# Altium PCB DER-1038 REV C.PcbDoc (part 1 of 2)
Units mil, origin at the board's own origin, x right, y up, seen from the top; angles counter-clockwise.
Board outline 9818.9 x 992.13 mil, 2 copper layers (TOP, BOTTOM), stack 10.4 mil thick; 94 components, 52 nets, 258 pads, 996 vias.
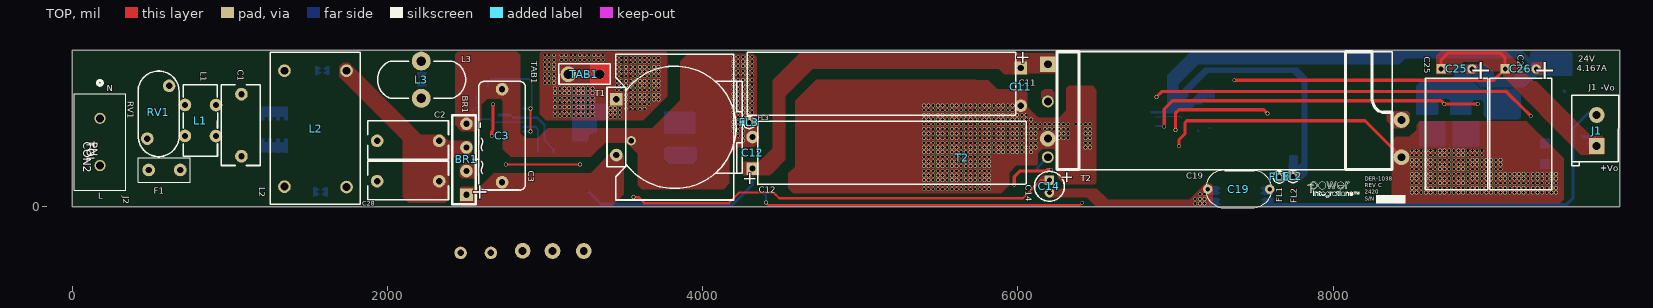
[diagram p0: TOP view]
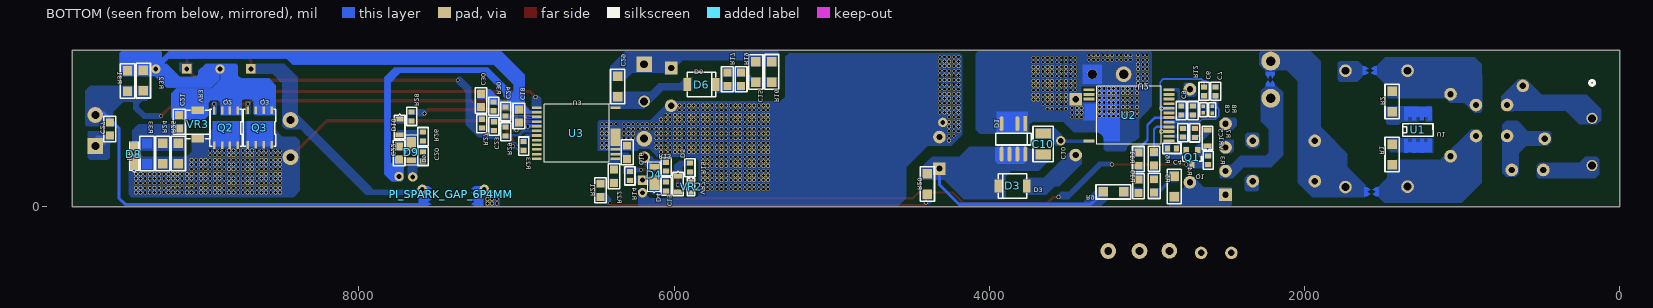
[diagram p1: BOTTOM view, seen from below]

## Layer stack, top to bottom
Top Solder: solder mask 0.4, Solder Resist, Dk 3.5
TOP: signal copper 1.2
Dielectric 1: core 8, FR-4, Dk 4.5
BOTTOM: signal copper 1.2
Bottom Solder: solder mask 0.4, Solder Resist, Dk 3.5

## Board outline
0,0 0,992.13 9818.9,992.13 9818.9,0

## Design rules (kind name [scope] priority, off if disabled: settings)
Clearance [All] p1: gap=10 ignorepadtopadclearanceinfootprint=FALSE
PlaneConnect [All] p1: planeconnectstyle=Direct reliefexpansion=20 reliefentries=4 reliefconductorwidth=10 reliefairgap=10
PolygonConnect [All] p1: connectstyle=Direct reliefconductorwidth=10 reliefentries=4 polygonreliefangle="90 Angle" airgapwidth=10
RoutingVias [All] p1: holewidth=28 width=50 viastyle="Through Hole" minholewidth=28 minwidth=50 maxholewidth=28 maxwidth=50
SolderMaskExpansion [All] p1: expansion=4 istentingtop=FALSE
Width [All] p1: maxlimit=10 minlimit=10 preferedwidth=10 impedanceprofiledriven=TRUE minimp=60.000000 maximp=60.000000 favimp=60.000000
29 further rules are at their usual default settings.

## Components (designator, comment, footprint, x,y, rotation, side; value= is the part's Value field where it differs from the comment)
BR1 "DISCRETE BRIDGE_+~~-_PIDAXBRIDG" PIDAXBRIDGED3K 2486,298.5 r90 top
C1 "CAP NP_PINPXCAPRAD13X6MM040_0.1" PINPXCAPRAD13X6MM040 1068.08,517.15 r270 top
C2 "CAP NP_PINPXCAPRAD13X6MM040_0.1" PINPXCAPRAD13X6MM040 2131.15,422.92 r180 top
C3 "CAP NP_PINPCAPRAD17P5X7P8X15MML" PINPCAPRAD17P5X7P8X15MMLS 2727,450.28 r90 top
C4 "CAP NP_PISMC0603_1 UF_UNISEM_RM" PISMC0603#1 2841,370 r180 bottom
C5 "CAP NP_PISMC0603_470 PF" PISMC0603#2 2771,469 r90 bottom
C6 "CAP NP_PISMC0603_1 UF_UNISEM_RM" PISMC0603#2 2637,732 r90 bottom
C7 "CAP NP_PISMC0603_0.1 UF_UNISEM_" PISMC0603#2 2564,732 r270 bottom
C8 "CAP NP_PISMR0402_1 UF_PISMR0402" PISMR0402 2641,616 r270 bottom
C9 "CAP NP_PISMC0603_470 PF" PISMC0603#2 2782,610 r270 bottom
C10 "CAP NP_PISMC1210_22 NF" PISMC1210 3658,396.75 r270 bottom
C11 "CAP POL_PIPOLCAPD395LS200D04017" PIPOLCAPD395LS200D0401705LH#1 5188.69,781.5 r270 top
C12 "CAP POL_PIPOLCAPD395LS200D04017" PIPOLCAPD395LS200D0401705LH#2 5147,340.5 r90 top
C13 "CAP NP_PISMC0603_NC_UNISEM_RMCF" PISMC0603#2 6051,129 r270 bottom
C14 "CAP POL_PI_POLCAP_D200_LS80_D03" PI_POLCAP_D200_LS80_D030 6201.37,131 r270 top
C15 "CAP NP_PISMC1206_2.2 NF_CAP_321" PISMC1206 5480.5,855 r90 bottom
C16 "CAP NP_PISMC0805_0.47 UF_UNISEM" PISMC0805 6298.37,345 r270 bottom
C18 "CAP NP_PISMC0805_2.2 UF" PISMC0805 6985.37,576 r270 bottom
C19 "CAP NP_PINPCAPRAD11X6MMD030_220" PINPCAPRAD11X6MMD030 7401.48,111.13 r0 top
C20 "CAP NP_PISMC0603_NC_UNISEM_RMCF" PISMC0603#2 7594,319 r270 bottom
C21 "CAP NP_PISMC0805_2200 PF_UNISEM" PISMC0805 9141,539 r90 bottom
C22 "CAP NP_PISMC0805_10 UF_UNISEM_R" PISMC0805 7745,341 r90 bottom
C23 "CAP NP_PISMC0603_22 NF_UNISEM_R" PISMC0603#2 7144,511 r270 bottom
C24 "CAP NP_PISMC0603_1 NF_UNISEM_RM" PISMC0603#2 7069,604 r270 bottom
C25 "CAP POL_PIPOLCAPCLYD10MMD30_680" PIPOLCAPCLYD10X18MMD30H 8783.89,509.83 r180 top
C26 "CAP POL_PIPOLCAPCLYD10MMD30_680" PIPOLCAPCLYD10X18MMD30H 9190.89,509.83 r180 top
C27 "CAP NP_PISMC0805_2.2 UF_UNISEM_" PISMC0805 9581,493 r270 bottom
C28 "CAP NP_PINPXCAPRAD13X6MM040_0.1" PINPXCAPRAD13X6MM040 2131.15,166.92 r180 top
C29 "CAP NP_PISMC1206_47 PF" PISMC1206 6358.5,763 r90 bottom
C30 "CAP NP_PISMC0805_2.2 UF" PISMC0805 7226,674 r90 bottom
D1 "DIODE_A1K8_PI_SM_DIODE_SO8C_LXA" PI_SM_DIODE_SO8C 3847,429 r0 bottom
D3 "DIODE_PISMDO221AA_STTH208UFY" PISMDO221AA#1 3852,132 r180 bottom
D4 "DIODE_PISMDDFLR120012_DFLR1200-" PISMDDFLR120012 6127,187 r90 bottom
D5 "DIODE_PISMSOD323_BAV19WS" PISMSOD323 5975,147.5 r90 bottom
D6 "DIODE_PISMDO221AA_GS1MFL-TP" PISMDO221AA#1 5826,775 r0 bottom
D8 "DIODE SCHOTTKY_PI_SM_SOD-123HE_" PI_SM_SOD-123HE 9428.5,319.94 r270 bottom
D9 "DIODE_PISMDDFLR120012_DFLR1200-" PISMDDFLR120012 7668,360 r270 bottom
D10 "DIODE_PISMSOD323_BAV19WS" PISMSOD323 7742,510.5 r90 bottom
F1 "FUSE_PI_RST_MICROFUSE_3.15 A_PI" PI_RST_MICROFUSE 582.9,233.08 r0 top
FL1 "FLYINGLEAD_PI_HOLE_30MIL_HOLE_3" PI_HOLE_30MIL 7659,188 r0 top
FL2 "FLYINGLEAD_PI_HOLE_30MIL_HOLE_3" PI_HOLE_30MIL 7746,191 r0 top
FL3 "FLYINGLEAD_PI_HOLE_30MIL_HOLE_3" PI_HOLE_30MIL 4295,534 r0 top
J1 "CON2_PI_TERM_BLOCK_2PIN_LS200_T" PI_TERM_BLOCK_2PIN_LS200 9663.75,483.5 r0 top
J2 "CON2_CONN_1707027_PXC_CON2" CONN_1707027_PXC 175,410.92 r270 top
L1 "TORRID 4P_14_23_PI_4P_LS5W4P8XD" PI_4P_LS5W4P8XD11P5MMD40 813,547 r269.91 top
L2 "INDUCTOR_4P_1-2_4-3_PIIND4P965X" PIIND4P965X571LS736X394D040 1542.5,498.5 r270 top
L3 "INDUCTOR_PI2P14DX6MMWD060_68 UH" PI2P14DX6MMWD060 2216.42,805.89 r270 top
PI_SPARK_GAP_6P4MM "" PI_SPARK_GAP_6P4MM#1 7413.63,116.31 r180.08 bottom
PI_SPARK_GAP_6P4MM "" PI_SPARK_GAP_6P4MM#2 7414.63,44 r179.99 bottom
Q1 "NPN_BEC_PISMSOT23123_1_MMBT4401" PISMSOT23123_1 2713.4,317.31 r0 bottom
Q2 "FET_N_SGD_123_4_5678_PISMPQFN5X" PISMPQFN5X6B 8843.5,502 r0 bottom
Q3 "FET_N_SGD_123_4_5678_PISMPQFN5X" PISMPQFN5X6B 8629.5,503 r0 bottom
R1 "R_PISMR1206_510 K" PISMR1206#1 1444.5,332 r270 bottom
R2 "R_PISMR1206_510 K" PISMR1206#1 1444.5,667 r270 bottom
R3 "R_PISMR0603_100 K" PISMR0603 2611,294.5 r270 bottom
R4 "R_PISMR1206_6.8 M" PISMR1206#1 2826.5,128 r90 bottom
R5 "R_PISMR0805_4.7 M_UNISEM_RMCF08" PISMR0805 2954,131.5 r90 bottom
R6 "R_PISMR0805_4.7 M_UNISEM_RMCF08" PISMR0805 2955,304.5 r270 bottom
R7 "R_PISMR0603_154 K_UNISEM_RMCF06" PISMR0603 2696,468.5 r90 bottom
R8 "R_PISMR0402_30.1 K" PISMR0402 2585,615 r90 bottom
R9 "R_PISMR1206_6.8 M" PISMR1206#2 3213,94.5 r180 bottom
R10 "R_PISMR0805_4.7 M_UNISEM_RMCF08" PISMR0805 3053,130.5 r270 bottom
R11 "R_PISMR0805_4.7 M_UNISEM_RMCF08" PISMR0805 3054,301.5 r90 bottom
R12 "R_PISMR0603_158 K_UNISEM_RMCF06" PISMR0603 2707,610.5 r90 bottom
R13 "R_PISMR0603_NC_UNISEM_RMCF0603U" PISMR0603 6051,253.5 r270 bottom
R14 "R_PISMR0603_5.1 K_UNISEM_RMCF06" PISMR0603 6281,194.5 r270 bottom
R15 "R_PISMR0603_100_UNISEM_RMCF0603" PISMR0603 5900,247.5 r270 bottom
R16 "R_PISMR1206_500 K" PISMR1206#1 5380.5,856 r90 bottom
R17 "R_PISMR0805_15_UNISEM_RMCF0805U" PISMR0805 5662,809.5 r270 bottom
R19 "R_PISMR0805_15_UNISEM_RMCF0805U" PISMR0805 5575,809.5 r270 bottom
R20 "R_PISMR1206_1.6 M" PISMR1206#1 4392.5,144 r90 bottom
R21 "R_PISMR0805_1.2 M_UNISEM_RMCF08" PISMR0805 6467.37,104.5 r270 bottom
R22 "R_PISMR0805_1.2 M_UNISEM_RMCF08" PISMR0805 6382,193.5 r270 bottom
R23 "R_PISMR0603_300_UNISEM_RMCF0603" PISMR0603 6955,384.5 r270 bottom
R24 "R_PISMR1206_15" PISMR1206#1 9244.5,337 r90 bottom
R25 "R_PISMR1206_15" PISMR1206#1 9145.5,338 r90 bottom
R26 "R_PISMR0603_NC_UNISEM_RMCF0603U" PISMR0603 7594,444.5 r270 bottom
R27 "R_PISMR0603_4.7 K_UNISEM_RMCF06" PISMR0603 7220,527.5 r90 bottom
R28 "R_PISMR0603_1.2 K_UNISEM_RMCF06" PISMR0603 7666,572.5 r270 bottom
R29 "R_PISMR0603_100 K" PISMR0603 7069,476.5 r270 bottom
R30 "R_PISMR0603_5.49 K_UNISEM_RMCF0" PISMR0603 7145,636.5 r270 bottom
R31 "R_PISMR1206_0.01" PISMR1206#1 9468.5,798 r90 bottom
R32 "R_PISMR1206_0.01" PISMR1206#1 9367.5,800 r90 bottom
R33 "R_PISMR1206_15" PISMR1206#3 9344.46,337 r90.04 bottom
RV1 "VARISTOR_PIDISC500X225LS335X140" PIDISC500X225LS335X140040 547.14,589.95 r270.1 top
T1 "BATQ23.2_4P/GENERIC_PI_BOBBIN_A" PI_BOBBIN_ATQ23_V_4PB 3822,505 r0 top
T2 "BEQ20_9P_PI_BOBBIN_EDR4110_9P_6" PI_BOBBIN_EDR4110_9P_6X3 7312.19,609 r0 top
TAB1 "CON1_2P_TAB_PI_CONN_QC_TAB_2PIN" PI_CONN_QC_TAB_2PIN_LS200 3250.44,840.94 r90.03 top
U1 "CAPZERO_PI_IC_SMD_SO8_CAPZERO_C" PI_IC_SMD_SO8_CAPZERO 1280.17,489.63 r180.1 bottom
U2 "HIPERPFS-4-INSOP24B_PI_IC_INSOP" PI_IC_INSOP24B 3114,580 r0 bottom
U3 "INNO4-QR_PI_IC_INSOP_24D_IPC_IN" PI_IC_INSOP_24D_IPC 6618.76,466.6 r180 bottom
VR1 "DIODE_ZENER_PISMSOD323_BZX384-B" PISMSOD323 2615,432.5 r270 bottom
VR2 "DIODE_ZENER_PI_SM_D_SSMINI2P_DZ" PI_SM_D_SSMINI2P 5892.51,131.5 r90 bottom
VR3 "DIODE_ZENER_PISMDO221AA_SMA6F10" PISMDO221AA#2 9023,522 r270 bottom

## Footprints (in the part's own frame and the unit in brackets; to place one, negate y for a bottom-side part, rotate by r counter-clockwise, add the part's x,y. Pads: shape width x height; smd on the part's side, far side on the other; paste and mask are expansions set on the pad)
CONN_1707027_PXC [mil] "CONN_1707027_PXC"
  round 71 hole 51: 1(-150,0) 2(150,0)
  silkscreen extent -390,-164 305,164, body extent -310,-169 310,169, height 150
PI2P14DX6MMWD060 [mil] "PI2P14DX6MMWD060"
  round 120 hole 60: 1(-118.11,-2.42) 2(118.11,-2.42)
  silkscreen extent -118,-279 118,280, body extent -181,-285 181,285, height 150
PI_4P_LS5W4P8XD11P5MMD40 [mil] "PI_4P_LS5W4P8XD11P5MMD40"
  round 80 hole 40: 1(-98.43,-98.43) 2(98.43,-98.43) 3(98.43,98.43) 4(-98.43,98.43)
  silkscreen extent -227,-110 226,108, body extent -226,-148 226,148, height 150
PI_BOBBIN_ATQ23_V_4PB [mil] "PI_BOBBIN_ATQ23_V_4PB"
  rect 80x80 / inner round 0 / far side rect 80x80 hole 40: 1(-370.08,177.16)
  round 80 hole 40: 2(-1166,-798) 3(-1358,-798) 4(-370.08,-177.17)
  silkscreen extent -429,-463 429,463, body extent -429,-386 429,386, height 150
PI_BOBBIN_EDR4110_9P_6X3 [mm] "PI_BOBBIN_EDR4110_9P_6X3"
  rect 2.54x2.54 / inner round 0 / far side rect 2.54x2.54 hole 1.27: 1(-28.495,7.5)
  round 2.54 hole 1.27: 2(-108.336,-22.606) 4(-113.152,-22.581) 5(-28.495,-4.5) 7(28.505,-7.5) 8(-103.307,-22.606) 9(28.505,-1.5)
  round 1.905 hole 1.27: 3(-28.495,1.5) 6(-28.495,-7.5)
  silkscreen extent -27,-9.5 27,9.5, body extent -30,-9.5 30,9.5, height 3.81
PI_CONN_QC_TAB_2PIN_LS200 [mil] "PI_CONN_QC_TAB_2PIN_LS200"
  round 61 / inner round 0 / far side round 61 hole 60: 1(0,-97.5)
  round 100 hole 60: 2(0,102.5)
  TOP region: 60,-37.5 -60,-37.5 -60,-157.5 60,-157.5
  BOTTOM region: 60,-37.5 -60,-37.5 -60,-157.5 60,-157.5
  silkscreen extent -65,-163 65,163, body extent -65,-163 65,163, height 150
PI_HOLE_30MIL [mil] "PI_HOLE_30MIL"
  round 60 hole 30: 1(0,1)
  silkscreen extent -38,-38 38,38
PI_IC_INSOP24B [mm] "PI_IC_INSOP24B"
  rect 1.75x0.45 smd: 1(-6.445,4.125) 2(-6.445,3.375) 3(-6.445,2.625) 4(-6.445,1.875) 5(-6.445,1.125) 6(-6.445,0.375) 7(-6.445,-0.375) 8(-6.445,-1.125) 9(-6.445,-1.875) 10(-6.445,-2.625) 11(-6.445,-3.375) 12(-6.445,-4.125) 13(6.445,-4.125) 14(6.445,-3.375) 15(6.445,-2.625) 24(6.445,4.125)
  round 0.025 smd: 16(6.445,-0.545)
  TOP region: 1.495,-4.15 1.495,4.15 4.045,4.15 4.045,4.05 4.144,3.553 4.426,3.131 4.848,2.849 5.345,2.75 5.345,2.75 5.445,2.75 5.445,0.8 7.1,0.8 7.1,-1.9 5.3,-1.9 5.3,-4.15
  TOP region: 7.319,0.809 7.319,0.55 7.121,0.55 7.121,-1.65 7.319,-1.65 7.319,-1.899 5.571,-1.899 5.571,0.809
  silkscreen extent -8.17,-4.7 5.22,4.7, body extent -7.57,-4.95 7.57,4.95, height 3.81
PI_IC_INSOP_24D_IPC [mm] "PI_IC_INSOP_24D_IPC"
  rect 1.58x0.409 smd: 1(-6.445,4.125) 2(-6.445,3.375) 3(-6.445,2.625) 4(-6.445,1.875) 5(-6.445,1.125) 6(-6.445,0.375) 7(-6.445,-0.375) 8(-6.445,-1.125) 9(-6.445,-1.875) 10(-6.445,-2.625) 11(-6.445,-3.375) 12(-6.445,-4.125) 13(6.275,-4.125) 14(6.275,-3.375) 15(6.275,-2.625) 24(6.275,4.125)
  rect 1.58x2.809 smd: 16(6.275,-0.675)
  silkscreen extent -6.65,-4.7 5.22,5, body extent -7.57,-4.95 7.57,4.95, height 3.81
PI_IC_SMD_SO8_CAPZERO [mil] "PI_IC_SMD_SO8_CAPZERO"
  round 1 smd: 1(-74.65,-102.76) 2(-24.65,-102.59) 3(25.35,-102.42) 4(75.35,-102.24) 5(74.64,102.46) 6(24.64,102.28) 7(-25.36,102.11) 8(-75.36,101.94)
  TOP region: -87.21,59.19 -87.5,145.2 86.49,145.8 86.79,59.8 62.79,59.72 62.72,79.72 -63.28,79.28 -63.21,59.27
  TOP region: 86.21,-59.2 86.5,-145.2 -87.49,-145.81 -87.8,-59.81 -63.8,-59.72 -63.73,-79.72 62.27,-79.29 62.2,-59.29
  TOP region: -63.71,145.28 -87.3,145.2 -87,58.6 -63.41,58.68
  TOP region: -63,-59.42 -86.6,-59.5 -86.3,-146.1 -62.7,-146.02
  TOP region: -13.71,145.45 -37.3,145.37 -37,58.77 -13.41,58.85
  TOP region: -13,-59.25 -36.6,-59.33 -36.3,-145.93 -12.7,-145.85
  TOP region: 36.29,145.62 12.7,145.54 13,58.94 36.59,59.03
  TOP region: 37,-59.08 13.4,-59.16 13.7,-145.75 37.3,-145.67
  TOP region: 86.29,145.8 62.7,145.72 62.99,59.12 86.59,59.2
  TOP region: 87,-58.9 63.4,-58.98 63.7,-145.58 87.3,-145.5
  silkscreen extent -96,-43 96,38, body extent -101,-153 101,153, height 150
PI_POLCAP_D200_LS80_D030 [mil] "PI_POLCAP_D200_LS80_D030"
  rect 60x60 / inner round 0 / far side rect 60x60 hole 30: 1(-38,-1)
  round 60 hole 30: 2(42,-1)
  silkscreen extent -93,-96 97,94, body extent -101,-101 101,101, height 150
PI_RST_MICROFUSE [mil] "PI_RST_MICROFUSE"
  round 80 hole 40: 1(-98.43,0) 2(101.57,0)
  silkscreen extent -163,-79 165,79, body extent -165,-79 165,79, height 150
PI_SM_D_SSMINI2P [mil] "PI_SM_D_SSMINI2P"
  rect 27.5x31.5 smd: 1(27.5,0.49) 2(-39.43,0.49)
  silkscreen extent -62,-24 61,25, body extent -67,-30 67,30, height 150
PI_SM_DIODE_SO8C [mil] "PI_SM_DIODE_SO8C"
  rect 25x94 smd: 1(-75,-98)
  oval 25x94 smd: 8(-75,95) ""(-25,-98) ""(-25,95) ""(25,95) ""(75,-98) ""(75,95)
  TOP region: -66,156 95,156 114,137 114,59 102,47 -80,47 -90,57 -90,132
  TOP region: -90,-34 107,-34 107,-173 -90,-173
  silkscreen extent -112,-38 112,38, body extent -116,-160 116,160, height 150
PI_SM_SOD-123HE [mil] "PI_SM_SOD-123HE"
  rect 102.4x55.1 smd: 1(34.94,0.5)
  rect 51.2x55.1 smd: 2(-61.52,0.5)
  silkscreen extent -89,-30 103,31, body extent -91,-32 91,33, height 150
PI_SPARK_GAP_6P4MM#1 [mil] "PI_SPARK_GAP_6P4MM"
  round 1 smd: 1(-166.25,-72.54) 1(-165.35,-0.47) 2(164.46,-72.1) 2(165.35,0.47)
  TOP region: -205.64,-58.81 -148.55,-58.73 -126.88,-72.48 -148.51,-86.29 -126.84,-102.01 -148.48,-111.88 -205.57,-111.96
  TOP region: -204.76,13.19 -147.68,13.36 -125.98,-0.36 -147.6,-14.2 -125.9,-29.89 -147.52,-39.79 -204.61,-39.96
  TOP region: 203.88,-111.41 146.79,-111.49 125.13,-101.68 146.76,-85.9 125.09,-72.15 146.72,-58.34 203.81,-58.26
  TOP region: 204.84,-38.78 147.75,-38.95 126.07,-29.17 147.68,-13.36 125.98,0.36 147.6,14.2 204.68,14.37
  body extent -197,-112 198,39, height 150
PI_SPARK_GAP_6P4MM#2 [mil] "PI_SPARK_GAP_6P4MM"
  round 1 smd: 1(-165.35,0.03) 1(-164.35,72.1) 2(165.35,-0.03) 2(166.36,72.53)
  TOP region: -204.72,13.82 -147.63,13.81 -125.98,0.03 -147.64,-13.75 -125.99,-29.5 -147.65,-39.34 -204.73,-39.33
  TOP region: -203.74,85.82 -146.65,85.9 -124.98,72.15 -146.61,58.34 -124.94,42.62 -146.58,32.75 -203.66,32.67
  TOP region: 204.72,-39.41 147.63,-39.4 125.98,-29.55 147.63,-13.81 125.98,-0.03 147.64,13.75 204.73,13.74
  TOP region: 205.78,33.22 148.7,33.14 127.03,42.96 148.66,58.73 126.99,72.48 148.63,86.29 205.71,86.37
  body extent -198,-39 197,112, height 150
PI_TERM_BLOCK_2PIN_LS200 [mil] "PI_TERM_BLOCK_2PIN_LS200"
  rect 100x100 / inner round 0 / far side rect 100x100 hole 50: 1(9.25,-98.5)
  round 100 hole 50: 2(9.25,98.4)
  silkscreen extent -148,-222 148,222
PIDAXBRIDGED3K [mil] "PIDAXBRIDGED3K"
  rect 80x80 / inner round 0 / far side rect 80x80 hole 40: 1(-222.5,-15)
  round 80 hole 40: 2(-72.5,-15) 3(77.5,-15) 4(227.5,-15)
  silkscreen extent -282,-97 282,75, body extent -282,-75 282,75, height 150
PIDISC500X225LS335X140040 [mil] "PIDISC500X225LS335X140040"
  round 80 hole 40: 1(-176.93,67.16) 2(158.07,-71.85)
  silkscreen extent -271,-130 272,130, body extent -272,-131 272,131, height 150
PIIND4P965X571LS736X394D040 [mil] "PIIND4P965X571LS736X394D040"
  round 80 hole 50: 1(371.5,-196.5) 2(373.69,197.5) 3(-364.5,197.5) 4(-364.5,-196.5)
  silkscreen extent -481,-287 483,284, body extent -490,-292 490,292, height 150
PINPCAPRAD11X6MMD030 [mil] "PINPCAPRAD11X6MMD030"
  round 60 hole 30: 1(-196.85,0) 2(196.85,0)
  silkscreen extent -207,-118 207,119, body extent -228,-119 228,119, height 150
PINPCAPRAD17P5X7P8X15MMLS [mil] "PINPCAPRAD17P5X7P8X15MMLS"
  round 80 hole 40: 1(-295.28,0) 2(295.28,0)
  silkscreen extent -345,-148 345,148, body extent -344,-148 344,148, height 150
PINPXCAPRAD13X6MM040 [mil] "PINPXCAPRAD13X6MM040"
  round 80 hole 40: 1(-196.85,4.92) 2(196.85,4.92)
  silkscreen extent -256,-123 256,123, body extent -256,-123 256,123, height 150
PIPOLCAPCLYD10X18MMD30H [mil] "PIPOLCAPCLYD10X18MMD30H"
  rect 60x60 / inner round 0 / far side rect 60x60 hole 30: 1(98.42,-364.17)
  round 60 hole 30: 2(-98.43,-364.17)
  silkscreen extent -197,-305 197,404, body extent -197,-404 197,404, height 150
PIPOLCAPD395LS200D0401705LH#1 [mil] "PIPOLCAPD395LS200D0401705LH"
  rect 80x80 / inner round 0 / far side rect 80x80 hole 40: 1(-98.5,830.44)
  round 80 hole 40: 2(140.87,830.44)
  silkscreen extent -200,-907 202,798, body extent -207,-911 207,911, height 150
PIPOLCAPD395LS200D0401705LH#2 [mil] "PIPOLCAPD395LS200D0401705LH"
  rect 80x80 / inner round 0 / far side rect 80x80 hole 40: 1(-98.5,830.44)
  round 80 hole 40: 2(101.5,830.44)
  silkscreen extent -200,-907 202,798, body extent -207,-911 207,911, height 150
PISMC0603#1 [mil] "PISMC0603"
  rect 32x38 smd: 1(-28,0) 2(28,0)
  silkscreen extent -58,-33 58,32, body extent -63,-38 63,38, height 150
PISMC0603#2 [mil] "PISMC0603"
  rect 32x38 smd: 1(28,0) 2(-28,0)
  silkscreen extent -58,-32 58,32, body extent -63,-38 63,38, height 150
PISMC0805 [mil] "PISMC0805"
  rect 50x50 smd: 1(42,0) 2(-42,0)
  silkscreen extent -80,-38 80,38, body extent -85,-44 85,44, height 150
PISMC1206 [mil] "PISMC1206"
  rect 60x60 smd: 1(65,0.5) 2(-65,0.5)
  silkscreen extent -110,-45 110,46, body extent -116,-51 116,51, height 150
PISMC1210 [mil] "PISMC1210"
  rect 64x100 smd: 1(66.75,0) 2(-68.25,0)
  silkscreen extent -114,-65 111,65, body extent -117,-68 117,68, height 150
PISMDDFLR120012 [mil] "PISMDDFLR120012"
  rect 90x60 smd: 1(-37,0)
  rect 36x60 smd: 2(66,0)
  silkscreen extent -97,-40 96,40, body extent -100,-44 100,44, height 150
PISMDO221AA#1 [mm] "PISMDO221AA"
  rect 1.2x2.07 smd: 1(-2.3,0) 2(2.3,0)
  silkscreen extent -2.3,-1.97 2.3,1.97, body extent -2.99,-1.97 2.99,1.97, height 3.81
PISMDO221AA#2 [mm] "PISMDO221AA"
  rect 1.2x2.07 smd: 1(2.3,0) 2(-2.3,0)
  silkscreen extent -2.3,-1.97 2.3,1.97, body extent -2.99,-1.97 2.99,1.97, height 3.81
PISMPQFN5X6B [mil] "PISMPQFN5X6B"
  rect 16x50 smd: 1(-74.5,-109) 2(-24.5,-109) 3(25.5,-109) 4(75.5,-109)
  rect 16x48 smd: 5(75.5,111) 6(25.5,111) 7(-24.5,111) 8(-74.5,111)
  TOP region: -81.5,-81 -81.5,-117 33.5,-117 33.5,-81
  TOP region: -82.5,3 -82.5,119 83.5,119 83.5,-40 -82.5,-40
  silkscreen extent -102,-150 104,120, body extent -110,-139 110,139, height 150
PISMR0402 [mil] "PISMR0402"
  rect 22x22 smd: 1(21,0) 2(-21,0)
  silkscreen extent -44,-23 44,23, body extent -49,-28 49,28, height 150
PISMR0603 [mil] "PISMR0603"
  rect 32x38 smd: 1(27.5,0) 2(-28.5,0)
  silkscreen extent -58,-32 57,33, body extent -58,-35 58,35, height 150
PISMR0805 [mil] "PISMR0805"
  rect 50x50 smd: 1(42.5,0) 2(-41.5,0)
  silkscreen extent -80,-38 80,38, body extent -82,-40 82,40, height 150
PISMR1206#1 [mil] "PISMR1206"
  rect 60x60 smd: 1(65,0.5) 2(-65,0.5)
  silkscreen extent -110,-45 110,46, body extent -116,-51 116,51, height 150
PISMR1206#2 [mil] "PISMR1206"
  rect 60x60 smd: 1(-65,-0.5) 2(65,-0.5)
  silkscreen extent -110,-46 110,45, body extent -116,-51 116,51, height 150
PISMR1206#3 [mil] "PISMR1206"
  round 1 smd: 1(65,0.59) 2(-65,0.41)
  TOP region: 95.04,-29.37 94.96,30.62 34.96,30.55 35.04,-29.45
  TOP region: -34.96,-29.55 -35.04,30.45 -95.04,30.37 -94.96,-29.63
  silkscreen extent -110,-45 110,46, body extent -116,-51 116,50, height 150
PISMSOD323 [mil] "PISMSOD323"
  rect 30x50 smd: 1(45.5,0) 2(-54.5,0)
  silkscreen extent -78,-34 78,34, body extent -84,-39 84,39, height 150
PISMSOT23123_1 [mil] "PISMSOT23123_1"
  rect 34x40 smd: 1(-37,-42) 2(37,-42)
  rect 34x50 smd: 3(0,48)
  silkscreen extent -60,-3 60,28, body extent -69,-77 69,77, height 150

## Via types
v1: diameter 24, hole 18, TOP to BOTTOM, 995 vias
v2: diameter 60, hole 35, TOP to BOTTOM, 1 vias

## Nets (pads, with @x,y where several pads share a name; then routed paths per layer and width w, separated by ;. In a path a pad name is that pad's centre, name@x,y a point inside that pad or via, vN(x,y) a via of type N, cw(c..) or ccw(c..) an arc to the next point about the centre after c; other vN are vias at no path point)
BPS: C18.1 R28.2 U3.4 | length 709.5
  TOP w20: v1(7000,486) 7000,592 7023,615 7560,615 v1(7584,591)
GND: C18.2 C21.1 C22.2 C24.2 C25.2 C26.2 C30.1 FL2.1 Q2.1 Q2.2 Q2.3 Q3.1 Q3.2 Q3.3 R30.2 R31.1 R32.1 U3.2 VR3.2
N13420620: C10.1 C11.1 C12.1 C15.1 C29.1 D1.8 D3.1 R9.1 R16.1 R20.1 T2.1 | length 1223.9
  BOTTOM w20: R9.1@3278,94 3356,16 4192,16 4316.56,140.56 C12.1@4316.56,242
N13420648: BR1.4 C3.2 C10.2 C11.2 C12.2 C14.2 C16.2 C19.1 FL3.1 T2.5 U2.24 U3.15 U3.16
  other v1: 7126.09,20.16 7155.61,20.16 7185.14,20.16 7126.09,49.69 7155.61,49.69 7185.14,49.69 7155.61,79.22 7185.14,79.22 5404.23,110.25 5433.76,110.25 5463.28,110.25 5492.81,110.25 5522.34,110.25 5551.87,110.25 5581.39,110.25 5610.92,110.25 5640.45,110.25 5669.98,110.25 5699.5,110.25 5729.03,110.25 5758.56,110.25 5788.09,110.25 5817.61,110.25 5404.23,139.78 5433.76,139.78 5463.28,139.78 5492.81,139.78 5522.34,139.78 5551.87,139.78 5581.39,139.78 5610.92,139.78 5640.45,139.78 5669.98,139.78 5699.5,139.78 5729.03,139.78 5758.56,139.78 5788.09,139.78 5817.61,139.78 5404.23,169.31 5433.76,169.31 5463.28,169.31 5492.81,169.31 5522.34,169.31 5551.87,169.31 5581.39,169.31 5610.92,169.31 5640.45,169.31 5669.98,169.31 5699.5,169.31 5729.03,169.31 5758.56,169.31 5788.09,169.31 5817.61,169.31 5404.23,198.84 5433.76,198.84 5463.28,198.84 5492.81,198.84 5522.34,198.84 5551.87,198.84 5581.39,198.84 5610.92,198.84 5640.45,198.84 5669.98,198.84 5699.5,198.84 5729.03,198.84 5758.56,198.84 5788.09,198.84 5817.61,198.84 5404.23,228.36 5433.76,228.36 5463.28,228.36 5492.81,228.36 5522.34,228.36 5551.87,228.36 5581.39,228.36 5610.92,228.36 5640.45,228.36 5669.98,228.36 5699.5,228.36 5729.03,228.36 5758.56,228.36 5788.09,228.36 5817.61,228.36 5404.23,257.89 5433.76,257.89 5463.28,257.89 5492.81,257.89 5522.34,257.89 5551.87,257.89 5581.39,257.89 5610.92,257.89 5640.45,257.89 5669.98,257.89 5699.5,257.89 5729.03,257.89 5758.56,257.89 5788.09,257.89 5817.61,257.89 5404.23,287.42 5433.76,287.42 5463.28,287.42 5492.81,287.42 5522.34,287.42 5551.87,287.42 5581.39,287.42 5610.92,287.42 5640.45,287.42 5669.98,287.42 5699.5,287.42 5729.03,287.42 5758.56,287.42 5788.09,287.42 5817.61,287.42 5404.23,316.94 5433.76,316.94 5463.28,316.94 5492.81,316.94 5522.34,316.94 5551.87,316.94 5581.39,316.94 5610.92,316.94 5640.45,316.94 5669.98,316.94 5699.5,316.94 5729.03,316.94 5758.56,316.94 5788.09,316.94 5817.61,316.94 5404.23,346.47 5433.76,346.47 5463.28,346.47 5492.81,346.47 5522.34,346.47 5551.87,346.47 5581.39,346.47 5610.92,346.47 5640.45,346.47 5669.98,346.47 5699.5,346.47 5729.03,346.47 5758.56,346.47 5788.09,346.47 5817.61,346.47 5847.14,346.47 5876.67,346.47 5906.2,346.47 5935.72,346.47 5965.25,346.47 5994.78,346.47 6024.31,346.47 6053.84,346.47 6083.36,346.47 5404.23,376 5433.76,376 5463.28,376 5492.81,376 5522.34,376 5551.87,376 5581.39,376 5610.92,376 5640.45,376 5669.98,376 5699.5,376 5729.03,376 5758.56,376 5788.09,376 5817.61,376 5847.14,376 5876.67,376 5906.2,376 5935.72,376 5965.25,376 5994.78,376 6024.31,376 6053.84,376 6083.36,376 6112.89,376 6429.06,376 6458.58,376 5404.23,405.53 5433.76,405.53 5463.28,405.53 5492.81,405.53 5522.34,405.53 5551.87,405.53 5581.39,405.53 5610.92,405.53 5640.45,405.53 5669.98,405.53 5699.5,405.53 5729.03,405.53 5758.56,405.53 5788.09,405.53 5817.61,405.53 5847.14,405.53 5876.67,405.53 5906.2,405.53 5935.72,405.53 5965.25,405.53 5994.78,405.53 6024.31,405.53 6053.84,405.53 6083.36,405.53 6112.89,405.53 6429.06,405.53 6458.58,405.53 4255.28,420.25 5404.23,435.06 5433.76,435.06 5463.28,435.06 5492.81,435.06 5522.34,435.06 5551.87,435.06 5581.39,435.06 5610.92,435.06 5640.45,435.06 5669.98,435.06 5699.5,435.06 5729.03,435.06 5758.56,435.06 5788.09,435.06 5817.61,435.06 5847.14,435.06 5876.67,435.06 5906.2,435.06 5935.72,435.06 5965.25,435.06 5994.78,435.06 6024.31,435.06 6053.84,435.06 6083.36,435.06 6112.89,435.06 6260.53,435.06 6290.06,435.06 6319.58,435.06 6429.06,435.06 6458.58,435.06 4225.76,449.78 4255.28,449.78 5404.23,464.58 5433.76,464.58 5463.28,464.58 5492.81,464.58 5522.34,464.58 5551.87,464.58 5581.39,464.58 5610.92,464.58 5640.45,464.58 5669.98,464.58 5699.5,464.58 5729.03,464.58 5758.56,464.58 5788.09,464.58 5817.61,464.58 5847.14,464.58 5876.67,464.58 5906.2,464.58 5935.72,464.58 5965.25,464.58 5994.78,464.58 6024.31,464.58 6053.84,464.58 6083.36,464.58 6112.89,464.58 6260.53,464.58 6290.06,464.58 6319.58,464.58 6429.06,464.58 6458.58,464.58 4196.23,479.31 4225.76,479.31 4255.28,479.31 5404.23,494.11 5433.76,494.11 5463.28,494.11 5492.81,494.11 5522.34,494.11 5551.87,494.11 5581.39,494.11 5610.92,494.11 5640.45,494.11 5669.98,494.11 5699.5,494.11 5729.03,494.11 5758.56,494.11 5788.09,494.11 5817.61,494.11 5847.14,494.11 5876.67,494.11 5906.2,494.11 5935.72,494.11 5965.25,494.11 5994.78,494.11 6024.31,494.11 6053.84,494.11 6083.36,494.11 6112.89,494.11 6142.42,494.11 6171.94,494.11 6201.47,494.11 6231,494.11 6260.53,494.11 6290.06,494.11 6319.58,494.11 6429.06,494.11 6458.58,494.11 4196.23,508.83 4225.76,508.83 4255.28,508.83 5404.23,523.64 5433.76,523.64 5463.28,523.64 5492.81,523.64 5522.34,523.64 5551.87,523.64 5581.39,523.64 5610.92,523.64 5640.45,523.64 5669.98,523.64 5699.5,523.64 5729.03,523.64 5758.56,523.64 5788.09,523.64 5817.61,523.64 5847.14,523.64 5876.67,523.64 5906.2,523.64 5935.72,523.64 5965.25,523.64 5994.78,523.64 6024.31,523.64 6053.84,523.64 6083.36,523.64 6112.89,523.64 6142.42,523.64 6171.94,523.64 6201.47,523.64 6231,523.64 6260.53,523.64 6290.06,523.64 6319.58,523.64 6370,523.64 6399.53,523.64 6429.06,523.64 6458.58,523.64 4196.23,538.36 4225.76,538.36 4255.28,538.36 5404.23,553.16 5433.76,553.16 5463.28,553.16 5492.81,553.16 5522.34,553.16 5551.87,553.16 5581.39,553.16 5610.92,553.16 5640.45,553.16 5669.98,553.16 5699.5,553.16 5729.03,553.16 5758.56,553.16 5788.09,553.16 5817.61,553.16 5847.14,553.16 5876.67,553.16 5906.2,553.16 5935.72,553.16 5965.25,553.16 5994.78,553.16 6024.31,553.16 6053.84,553.16 6083.36,553.16 4196.23,567.89 4225.76,567.89 4255.28,567.89 5404.23,582.69 5433.76,582.69 5463.28,582.69 5492.81,582.69 5522.34,582.69 5551.87,582.69 5581.39,582.69 5610.92,582.69 5640.45,582.69 5669.98,582.69 5699.5,582.69 5729.03,582.69 5758.56,582.69 5788.09,582.69 5817.61,582.69 5847.14,582.69 5876.67,582.69 5906.2,582.69 5935.72,582.69 5965.25,582.69 5994.78,582.69 6024.31,582.69 6053.84,582.69 4196.23,597.42 4225.76,597.42 4255.28,597.42 4284.81,597.42 4314.34,597.42 5404.23,612.22 5433.76,612.22 5463.28,612.22 5492.81,612.22 5522.34,612.22 5551.87,612.22 5581.39,612.22 5610.92,612.22 5640.45,612.22 5669.98,612.22 5699.5,612.22 5729.03,612.22 5758.56,612.22 5788.09,612.22 5817.61,612.22 5847.14,612.22 5876.67,612.22 5906.2,612.22 5935.72,612.22 5965.25,612.22 4196.23,626.95 4225.76,626.95 4255.28,626.95 4284.81,626.95 4314.34,626.95 5404.23,641.75 5433.76,641.75 5463.28,641.75 5492.81,641.75 5522.34,641.75 5551.87,641.75 5581.39,641.75 5610.92,641.75 5640.45,641.75 5669.98,641.75 5699.5,641.75 5729.03,641.75 5758.56,641.75 5788.09,641.75 5817.61,641.75 5847.14,641.75 5876.67,641.75 5906.2,641.75 5935.72,641.75 5965.25,641.75 4196.23,656.47 4225.76,656.47 4255.28,656.47 4284.81,656.47 4314.34,656.47 4196.23,686 4225.76,686 4255.28,686 4284.81,686 4314.34,686 4196.23,715.53 4225.76,715.53 4255.28,715.53 4284.81,715.53 4314.34,715.53 4196.23,745.05 4225.76,745.05 4255.28,745.05 4284.81,745.05 4314.34,745.05 4196.23,774.58 4225.76,774.58 4255.28,774.58 4284.81,774.58 4314.34,774.58 4196.23,804.11 4225.76,804.11 4255.28,804.11 4284.81,804.11 4314.34,804.11 4196.23,833.64 4225.76,833.64 4255.28,833.64 4284.81,833.64 4314.34,833.64 4196.23,863.16 4225.76,863.16 4255.28,863.16 4284.81,863.16 4314.34,863.16 4196.23,892.69 4225.76,892.69 4255.28,892.69 4284.81,892.69 4314.34,892.69 4196.23,922.22 4225.76,922.22 4255.28,922.22 4284.81,922.22 4314.34,922.22 4196.23,951.75 4225.76,951.75 4255.28,951.75 4284.81,951.75 4314.34,951.75
  other v2: 3546.4,417.6
N13420656: C19.2 C25.1 C26.1 C27.1 C30.2 J1.1 R27.1 R29.1 T2.9 U3.6 | length 2457.1
  TOP w20: v1(7373.74,802) 9020.47,802 C26.1@9092.47,874 9092.47,943.68 9060.15,976 8732,976 8685.47,929.47 C25.1@8685.47,874
  BOTTOM w20: C27.1@9581,451 9590,442 9661.85,442 9620,400.15
N13421012: C23.2 C24.1 R29.2 R30.1 U3.3 | length 169.3
  BOTTOM w6.14: U3.3@6872.5,569.95 6916.67,569.95 6920.8,574.07 7027.23,574.07 7036.3,565
N13421042: C23.1 R27.2 | length 7.2
  BOTTOM w12: C23.1@7144,483 C23.1@7147,480 ; R27.2@7217,499 R27.2@7220,499
N13421702: C21.2 D8.2 R24.1 R25.1 R33.1
N13421894: D8.1 Q2.5 Q2.6 Q2.7 Q2.8 Q3.5 Q3.6 Q3.7 Q3.8 R23.1 R24.2 R25.2 R33.2 T2.7 VR3.1 | length 1639.5
  TOP w20: v1(7023,384) 7023,424 7061,462 7061,534 7072,545 8203.14,545 T2.7@8434.42,313.72
  other v1: 8501.09,90 8530.61,90 8560.14,90 8589.67,90 8619.2,90 8648.72,90 8855.09,90 8884.61,90 8914.14,90 8943.67,90 8973.2,90 9002.72,90 9033.09,90.06 9062.61,90.06 9092.14,90.06 9121.67,90.06 9151.2,90.06 9180.72,90.06 9209.09,89.64 9238.61,89.64 9268.14,89.64 9297.67,89.64 9327.2,89.64 9356.72,89.64 9386.09,89.64 9415.61,89.64 8678.09,91 8707.61,91 8737.14,91 8766.67,91 8796.2,91 8825.72,91 9209.09,119.17 9238.61,119.17 9268.14,119.17 9297.67,119.17 9327.2,119.17 9356.72,119.17 9386.09,119.17 9415.61,119.17 8501.09,119.53 8530.61,119.53 8560.14,119.53 8589.67,119.53 8619.2,119.53 8648.72,119.53 8855.09,119.53 8884.61,119.53 8914.14,119.53 8943.67,119.53 8973.2,119.53 9002.72,119.53 9033.09,119.58 9062.61,119.58 9092.14,119.58 9121.67,119.58 9151.2,119.58 9180.72,119.58 8678.09,120.53 8707.61,120.53 8737.14,120.53 8766.67,120.53 8796.2,120.53 8825.72,120.53 8501.09,149.06 8530.61,149.06 8560.14,149.06 8589.67,149.06 8619.2,149.06 8648.72,149.06 8855.09,149.06 8884.61,149.06 8914.14,149.06 8943.67,149.06 8973.2,149.06 9002.72,149.06 9033.09,149.11 9062.61,149.11 9092.14,149.11 9121.67,149.11 9151.2,149.11 9180.72,149.11 9209.09,148.69 9238.61,148.69 9268.14,148.69 9297.67,148.69 9327.2,148.69 9356.72,148.69 9386.09,148.69 9415.61,148.69 8678.09,150.06 8707.61,150.06 8737.14,150.06 8766.67,150.06 8796.2,150.06 8825.72,150.06 9209.09,178.22 9238.61,178.22 9268.14,178.22 9297.67,178.22 9327.2,178.22 9356.72,178.22 9386.09,178.22 9415.61,178.22 8501.09,178.58 8530.61,178.58 8560.14,178.58 8589.67,178.58 8619.2,178.58 8648.72,178.58 8855.09,178.58 8884.61,178.58 8914.14,178.58 8943.67,178.58 8973.2,178.58 9002.72,178.58 9033.09,178.64 9062.61,178.64 9092.14,178.64 9121.67,178.64 9151.2,178.64 9180.72,178.64 8678.09,179.58 8707.61,179.58 8737.14,179.58 8766.67,179.58 8796.2,179.58 8825.72,179.58 8501.09,208.11 8530.61,208.11 8560.14,208.11 8589.67,208.11 8619.2,208.11 8648.72,208.11 8855.09,208.11 8884.61,208.11 8914.14,208.11 8943.67,208.11 8973.2,208.11 9002.72,208.11 9033.09,208.16 9062.61,208.16 9092.14,208.16 9121.67,208.16 9151.2,208.16 9180.72,208.16 9209.09,207.75 9238.61,207.75 9268.14,207.75 9297.67,207.75 9327.2,207.75 9356.72,207.75 9386.09,207.75 9415.61,207.75 8678.09,209.11 8707.61,209.11 8737.14,209.11 8766.67,209.11 8796.2,209.11 8825.72,209.11 8501.09,237.64 8530.61,237.64 8560.14,237.64 8589.67,237.64 8619.2,237.64 8648.72,237.64 8855.09,237.64 8884.61,237.64 8914.14,237.64 8943.67,237.64 8973.2,237.64 9002.72,237.64 9033.09,237.69 9062.61,237.69 8678.09,238.64 8707.61,238.64 8737.14,238.64 8766.67,238.64 8796.2,238.64 8825.72,238.64 8501.09,267.17 8530.61,267.17 8560.14,267.17 8589.67,267.17 8619.2,267.17 8648.72,267.17 8855.09,267.17 8884.61,267.17 8914.14,267.17 8943.67,267.17 8973.2,267.17 9002.72,267.17 9033.09,267.22 9062.61,267.22 8678.09,268.17 8707.61,268.17 8737.14,268.17 8766.67,268.17 8796.2,268.17 8825.72,268.17 8501.09,296.69 8530.61,296.69 8560.14,296.69 8589.67,296.69 8619.2,296.69 8648.72,296.69 8855.09,296.69 8884.61,296.69 8914.14,296.69 8943.67,296.69 8973.2,296.69 9002.72,296.69 9033.09,296.75 9062.61,296.75 8678.09,297.69 8707.61,297.69 8737.14,297.69 8766.67,297.69 8796.2,297.69 8825.72,297.69 8501.09,326.22 8530.61,326.22 8560.14,326.22 8589.67,326.22 8619.2,326.22 8648.72,326.22 8855.09,326.22 8884.61,326.22 8914.14,326.22 8943.67,326.22 8678.09,327.22 8707.61,327.22 8737.14,327.22 8766.67,327.22 8796.2,327.22 8825.72,327.22 8501.09,355.75 8530.61,355.75 8560.14,355.75 8589.67,355.75 8619.2,355.75 8648.72,355.75 8855.09,355.75 8884.61,355.75 8914.14,355.75 8943.67,355.75 8678.09,356.75 8707.61,356.75 8737.14,356.75 8766.67,356.75 8796.2,356.75 8825.72,356.75
N13422446: Q2.4 Q3.4 U3.5 | length 2189.5
  TOP w20: v1(6929,508) 6929,620 6981,672 8686,672 v1(8706,652) v1(8919,652)
  BOTTOM w10: U3.5@6872.5,510.89 U3.5@6888,510.89
  BOTTOM w12: U3.5@6888,510.89 6926.11,510.89 v1(6929,508)
N13423706: C16.1 R14.2 U3.14 VR2.2 | length 302.1
  TOP w20: v1(5977,139) 5977,189 6015,227 6179,227 6187,235 v1(6210,235)
N13423710: C20.1 D9.2 FL1.1
N13423714: C22.1 D9.1 D10.2 R26.2
N13440082: D10.1 R28.1
N13449363: D4.2 R13.2 T2.6 | length 100.3
  BOTTOM w20: D4.2@6125,240.46 6125,248.4 T2.6@6190.32,313.72
N13473411: R15.1 VR2.1
N13473415: D5.1 R15.2
N13513324: C27.2 J1.2 R31.2 R32.2 U3.1 | length 4999.9
  TOP w20: v1(6880,697) 6913.49,730.49 9099.51,730.49 9225,605 9226,605 v1(9255,576)
  BOTTOM w20: 7589,42 7616,15 9484,15 9523,54 9523,498.09 9621.15,596.24 ; R31.2@9467,735 R31.2@9469,733
N13515268: C13.2 R13.1
N13515819: C20.2 R26.1
N13523750: R20.2 R21.1 | length 2075.9
  TOP w12: v1(4401,26) 4416.68,10.32 6393.32,10.32 v1(6408,25)
  BOTTOM w12: R20.2@4393,79 4401,71 v1(4401,26)
N13523772: R21.2 R22.1
N13523865: R22.2 U3.13
N13911889: C15.2 R16.2 R17.2 R19.2
N13911953: D6.1 R17.1 R19.1
N13912909: C29.2 D6.2 T2.3 U3.24
N13916087: R23.2 U3.7
N13925544: BR1.2 L3.2
N13925608: BR1.3 C2.1 C28.1 L2.3
N13925722: C2.2 C28.2 L2.2 L3.1
N13925782: C1.2 L1.3 L2.1 R1.1
N13925794: C1.1 L1.4 L2.4 R2.2
N13925904: R1.2 U1.1 U1.2 U1.3 U1.4
N13925908: R2.1 U1.5 U1.7 U1.8
N13925956: F1.2 L1.2 RV1.2
N13925960: J2.1 L1.1 RV1.1
N13926028: F1.1 J2.2
N13967468: BR1.1 C3.1 D3.2 R4.2 T1.4
N13967702: R9.2 R10.1
N13967706: R4.1 R5.2
N13967710: C9.1 R11.1 R12.2 U2.6 | length 513.5
  BOTTOM w15: C9.1@2782,582 2798.76,565.24 U2.6@2860.26,565.24 2948.76,565.24 2996,518 2996,423 3054,365 R11.1@3054,344
  BOTTOM w20: R12.2@2707,582 C9.1@2782,582
N13967734: C6.1 U2.3 U2.8 | length 739.9
  TOP w15: v1(2907,623) 2907,503.5 2907.35,503.16 v1(2907.35,476.65)
  BOTTOM w10: v1(2907,623) v1@2908,623
  BOTTOM w12: C6.1@2637,760 2637,792 2656,811 2895,811 2915,791 2915,631 v1(2907,623) 2906.35,622.35 2862.2,622.35 U2.8@2860.26,624.29 ; U2.3@2860.26,476.65 v1(2907.35,476.65)
N13967764: C7.1 R8.1 U2.5 | length 500.4
  BOTTOM w10: C7.1@2564,704 2564,673 2574,663 2574,647 R8.1@2585,636 2580,631 2555,631 2545,621 2545,575 2565,555 2649.71,555 2669,535.71 U2.5@2860.26,535.71
N13967780: R5.1 R6.1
